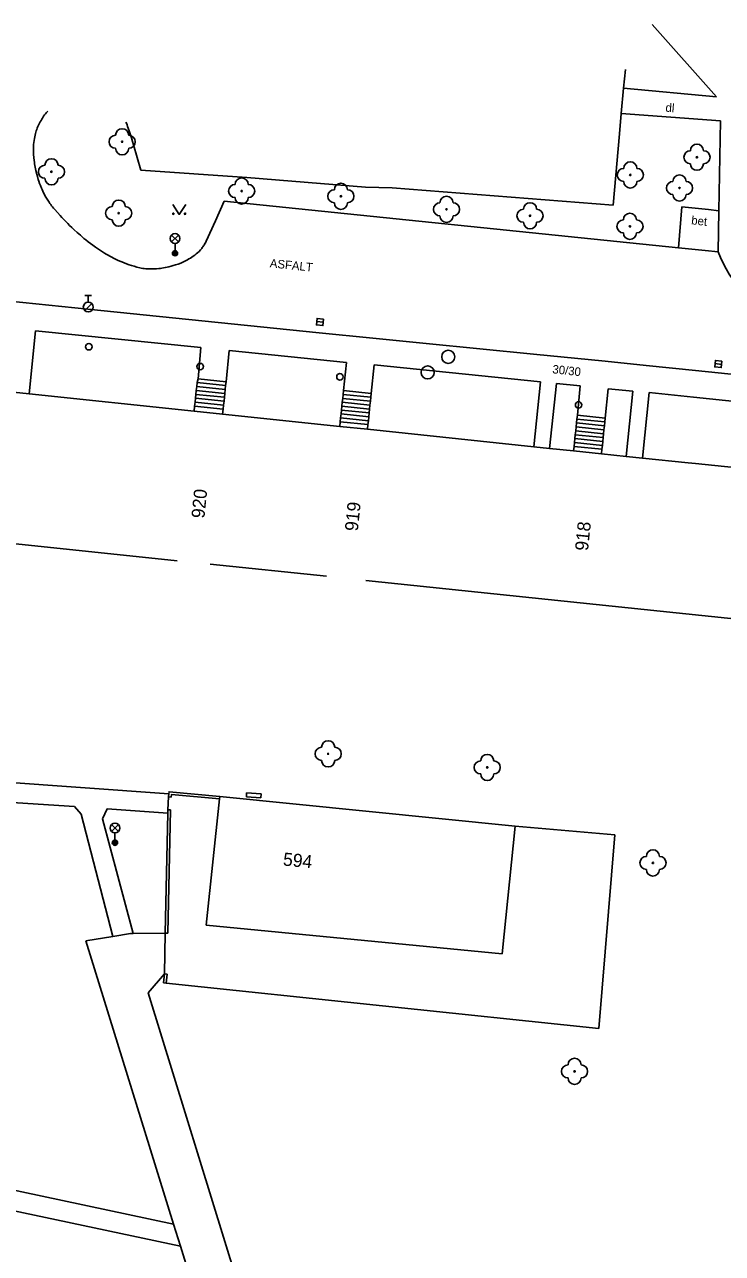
# Model space of a CAD drawing. Extents: x -539244 to -537359, y -1183785 to -1181851.
# Drawn here: x -537529.3 to -537476, y -1181981.5 to -1181887.6 of the extents above; entities that cross this region are included whole.
import ezdxf

# ---------------------------------------------------------------- set-up
doc = ezdxf.new("R2010")
doc.units = 0
for name, color, linetype in [('Vrstva 10', 7, 'Continuous'), ('Vrstva 11', 7, 'Continuous'), ('Vrstva 22', 7, 'Continuous'), ('Vrstva 24', 7, 'Continuous'), ('Vrstva 27', 7, 'Continuous'), ('Vrstva 28', 7, 'Continuous'), ('Vrstva 33', 7, 'Continuous'), ('Vrstva 36', 7, 'Continuous'), ('Vrstva 40', 7, 'Continuous'), ('Vrstva 47', 7, 'Continuous'), ('Vrstva 5', 7, 'Continuous'), ('Vrstva 7', 7, 'Continuous'), ('Vrstva 8', 7, 'Continuous')]:
    doc.layers.add(name, color=color, linetype=linetype)

msp = doc.modelspace()

# ---------------------------------------------------------------- linework, layer by layer
at = {"layer": 'Vrstva 10'}
for p, q in [((-537524.45, -1181909.37), (-537542.12, -1181907.57)), ((-537506.78, -1181911.17), (-537524.45, -1181909.37)), ((-537490.387, -1181912.801), (-537498.584, -1181911.992)), ((-537484.922, -1181913.344), (-537490.387, -1181912.801)), ((-537470.253, -1181914.859), (-537478.01, -1181914.046)), ((-537518.58, -1181960.12), (-537519.84, -1181961.58)), ((-537507.948, -1182000.008), (-537519.84, -1181961.58))]:
    msp.add_line(p, q, dxfattribs=at)
for points in [[(-537528.132, -1181899.754), (-537528.185, -1181899.6), (-537528.227, -1181899.465), (-537528.296, -1181899.228), (-537528.342, -1181899.049), (-537528.405, -1181898.78), (-537528.46, -1181898.51), (-537528.484, -1181898.381), (-537528.505, -1181898.256), (-537528.524, -1181898.133), (-537528.541, -1181898.013), (-537528.567, -1181897.779), (-537528.585, -1181897.558), (-537528.595, -1181897.349), (-537528.597, -1181897.152), (-537528.593, -1181896.966), (-537528.583, -1181896.792), (-537528.568, -1181896.628), (-537528.549, -1181896.475), (-537528.526, -1181896.331), (-537528.5, -1181896.196), (-537528.471, -1181896.069), (-537528.441, -1181895.951), (-537528.41, -1181895.84), (-537528.377, -1181895.737), (-537528.344, -1181895.64), (-537528.31, -1181895.549), (-537528.277, -1181895.464), (-537528.208, -1181895.306), (-537528.141, -1181895.168), (-537528.077, -1181895.048), (-537528.018, -1181894.944), (-537527.963, -1181894.853), (-537527.912, -1181894.774), (-537527.818, -1181894.636), (-537527.742, -1181894.533), (-537527.683, -1181894.457), (-537527.589, -1181894.343), (-537527.49, -1181894.23)], [(-537521.1, -1181906.029), (-537521.293, -1181905.965), (-537521.479, -1181905.898), (-537521.659, -1181905.829), (-537521.833, -1181905.758), (-537522.002, -1181905.686), (-537522.164, -1181905.612), (-537522.321, -1181905.537), (-537522.473, -1181905.462), (-537522.62, -1181905.385), (-537522.762, -1181905.309), (-537522.899, -1181905.233), (-537523.031, -1181905.156), (-537523.159, -1181905.08), (-537523.407, -1181904.927), (-537523.638, -1181904.776), (-537523.853, -1181904.628), (-537524.054, -1181904.484), (-537524.242, -1181904.345), (-537524.418, -1181904.21), (-537524.582, -1181904.08), (-537524.735, -1181903.956), (-537524.879, -1181903.836), (-537525.013, -1181903.722), (-537525.263, -1181903.501), (-537525.48, -1181903.302), (-537525.669, -1181903.123), (-537525.834, -1181902.962), (-537525.978, -1181902.82), (-537526.229, -1181902.563), (-537526.415, -1181902.366), (-537526.555, -1181902.216), (-537526.763, -1181901.985), (-537526.97, -1181901.75), (-537527.054, -1181901.651), (-537527.132, -1181901.555), (-537527.205, -1181901.462), (-537527.274, -1181901.372), (-537527.338, -1181901.285), (-537527.397, -1181901.2), (-537527.507, -1181901.035), (-537527.604, -1181900.88), (-537527.689, -1181900.735), (-537527.763, -1181900.598), (-537527.829, -1181900.47), (-537527.888, -1181900.349), (-537527.94, -1181900.236), (-537527.986, -1181900.13), (-537528.067, -1181899.93), (-537528.132, -1181899.754)], [(-537514.03, -1181901.108), (-537514.7, -1181902.605), (-537515.4, -1181904.17), (-537515.436, -1181904.247), (-537515.475, -1181904.322), (-537515.516, -1181904.394), (-537515.558, -1181904.464), (-537515.602, -1181904.532), (-537515.648, -1181904.597), (-537515.695, -1181904.661), (-537515.743, -1181904.722), (-537515.793, -1181904.781), (-537515.843, -1181904.838), (-537515.948, -1181904.947), (-537516.055, -1181905.049), (-537516.163, -1181905.144), (-537516.274, -1181905.233), (-537516.384, -1181905.315), (-537516.495, -1181905.392), (-537516.606, -1181905.464), (-537516.716, -1181905.53), (-537516.825, -1181905.592), (-537516.933, -1181905.65), (-537517.039, -1181905.703), (-537517.144, -1181905.753), (-537517.246, -1181905.799), (-537517.347, -1181905.842), (-537517.545, -1181905.919), (-537517.734, -1181905.985), (-537517.913, -1181906.041), (-537518.082, -1181906.089), (-537518.241, -1181906.129), (-537518.39, -1181906.163), (-537518.531, -1181906.191), (-537518.662, -1181906.214), (-537518.785, -1181906.233), (-537518.9, -1181906.249), (-537519.007, -1181906.261), (-537519.206, -1181906.279), (-537519.378, -1181906.289), (-537519.526, -1181906.293), (-537519.654, -1181906.293), (-537519.764, -1181906.29), (-537519.859, -1181906.286), (-537520.022, -1181906.273), (-537520.141, -1181906.26), (-537520.229, -1181906.248), (-537520.356, -1181906.226), (-537520.48, -1181906.2), (-537520.694, -1181906.147), (-537520.9, -1181906.09), (-537521.1, -1181906.029)], [(-537514.03, -1181901.108), (-537479.327, -1181904.669), (-537477.276, -1181904.88), (-537476.3, -1181904.98)], [(-537476.3, -1181904.98), (-537476.113, -1181905.419), (-537475.907, -1181905.851), (-537475.682, -1181906.275), (-537475.439, -1181906.689), (-537475.179, -1181907.093), (-537474.901, -1181907.485), (-537474.608, -1181907.865), (-537474.3, -1181908.231), (-537473.977, -1181908.582)], [(-537498.584, -1181911.992), (-537502.682, -1181911.584), (-537506.78, -1181911.17)], [(-537478.01, -1181914.046), (-537481.8, -1181913.658), (-537484.922, -1181913.344)], [(-537524.59, -1181957.61), (-537522.536, -1181957.261), (-537521.18, -1181957.03), (-537520.978, -1181957.029), (-537518.53, -1181957.02)], [(-537511.162, -1182001.003), (-537517.374, -1181980.928), (-537517.896, -1181979.241), (-537524.59, -1181957.61)]]:
    msp.add_lwpolyline(points, dxfattribs=at)
at = {"layer": 'Vrstva 11'}
for p, q in [((-537481.34, -1181887.63), (-537476.42, -1181893.14)), ((-537476.42, -1181893.14), (-537483.512, -1181892.493)), ((-537483.688, -1181894.425), (-537476.11, -1181894.977)), ((-537476.238, -1181901.843), (-537476.11, -1181894.977)), ((-537484.31, -1181901.41), (-537483.83, -1181895.98)), ((-537520.4, -1181898.75), (-537512.3, -1181899.31)), ((-537503.22, -1181900.04), (-537512.3, -1181899.31)), ((-537503.22, -1181900.04), (-537501.18, -1181900.1)), ((-537501.18, -1181900.1), (-537484.31, -1181901.41)), ((-537479.327, -1181904.669), (-537479.07, -1181901.55)), ((-537476.3, -1181904.98), (-537476.238, -1181901.843)), ((-537528.928, -1181915.831), (-537528.43, -1181911.01)), ((-537515.82, -1181912.29), (-537528.43, -1181911.01)), ((-537513.886, -1181914.9), (-537513.64, -1181912.52)), ((-537504.69, -1181913.44), (-537513.64, -1181912.52)), ((-537504.911, -1181915.577), (-537504.69, -1181913.44)), ((-537502.795, -1181915.796), (-537502.57, -1181913.62)), ((-537489.85, -1181914.9), (-537502.57, -1181913.62)), ((-537513.947, -1181915.496), (-537516.127, -1181915.271)), ((-537513.916, -1181915.198), (-537516.096, -1181914.973)), ((-537513.886, -1181914.9), (-537516.02, -1181914.68)), ((-537490.363, -1181919.867), (-537489.85, -1181914.9)), ((-537489.162, -1181919.993), (-537488.65, -1181915.03)), ((-537486.82, -1181915.22), (-537488.65, -1181915.03)), ((-537514.039, -1181916.392), (-537516.219, -1181916.167)), ((-537514.009, -1181916.093), (-537516.189, -1181915.868)), ((-537513.978, -1181915.795), (-537516.158, -1181915.57)), ((-537502.856, -1181916.392), (-537504.972, -1181916.173)), ((-537502.825, -1181916.094), (-537504.941, -1181915.875)), ((-537502.795, -1181915.796), (-537504.911, -1181915.577)), ((-537484.92, -1181917.678), (-537484.69, -1181915.45)), ((-537484.69, -1181915.45), (-537482.8, -1181915.62)), ((-537483.314, -1181920.605), (-537482.8, -1181915.62)), ((-537482.076, -1181920.734), (-537481.56, -1181915.73)), ((-537514.101, -1181916.988), (-537516.281, -1181916.763)), ((-537514.07, -1181916.69), (-537516.25, -1181916.465)), ((-537502.949, -1181917.288), (-537505.065, -1181917.069)), ((-537502.918, -1181916.989), (-537505.034, -1181916.77)), ((-537502.887, -1181916.691), (-537505.003, -1181916.472)), ((-537503.042, -1181918.183), (-537505.158, -1181917.964)), ((-537503.011, -1181917.884), (-537505.127, -1181917.665)), ((-537502.98, -1181917.586), (-537505.096, -1181917.367)), ((-537484.981, -1181918.274), (-537487.112, -1181918.054)), ((-537484.95, -1181917.976), (-537487.082, -1181917.756)), ((-537484.92, -1181917.678), (-537487.03, -1181917.46)), ((-537485.074, -1181919.17), (-537487.205, -1181918.95)), ((-537485.043, -1181918.871), (-537487.174, -1181918.651)), ((-537485.012, -1181918.573), (-537487.143, -1181918.353)), ((-537485.166, -1181920.065), (-537487.297, -1181919.845)), ((-537485.135, -1181919.766), (-537487.267, -1181919.546)), ((-537485.105, -1181919.468), (-537487.236, -1181919.248)), ((-537541.93, -1181944.68), (-537518.255, -1181946.366)), ((-537525.47, -1181947.35), (-537542.09, -1181946.28)), ((-537524.96, -1181947.93), (-537525.47, -1181947.35)), ((-537522.536, -1181957.261), (-537524.96, -1181947.93)), ((-537523.33, -1181948.29), (-537520.978, -1181957.029)), ((-537564.02, -1181969.4), (-537517.896, -1181979.241)), ((-537517.374, -1181980.928), (-537563.82, -1181971.03))]:
    msp.add_line(p, q, dxfattribs=at)
for points in [[(-537483.83, -1181895.98), (-537483.688, -1181894.425), (-537483.512, -1181892.493), (-537483.38, -1181891.05)], [(-537521.528, -1181895.077), (-537521.495, -1181895.157), (-537521.447, -1181895.278), (-537521.404, -1181895.402), (-537521.288, -1181895.756), (-537521.118, -1181896.289), (-537521.037, -1181896.555), (-537520.958, -1181896.823), (-537520.679, -1181897.786), (-537520.4, -1181898.75)], [(-537479.07, -1181901.55), (-537477.026, -1181901.761), (-537476.238, -1181901.843)], [(-537516.02, -1181914.68), (-537515.82, -1181912.29)], [(-537516.321, -1181917.15), (-537516.281, -1181916.763), (-537516.25, -1181916.465), (-537516.219, -1181916.167), (-537516.189, -1181915.868), (-537516.158, -1181915.57), (-537516.127, -1181915.271), (-537516.096, -1181914.973), (-537516.02, -1181914.68)], [(-537514.142, -1181917.378), (-537514.101, -1181916.988), (-537514.07, -1181916.69), (-537514.039, -1181916.392), (-537514.009, -1181916.093), (-537513.978, -1181915.795), (-537513.947, -1181915.496), (-537513.916, -1181915.198), (-537513.886, -1181914.9)], [(-537487.03, -1181917.46), (-537486.82, -1181915.22)], [(-537505.193, -1181918.315), (-537505.158, -1181917.964), (-537505.127, -1181917.665), (-537505.096, -1181917.367), (-537505.065, -1181917.069), (-537505.034, -1181916.77), (-537505.003, -1181916.472), (-537504.972, -1181916.173), (-537504.941, -1181915.875), (-537504.911, -1181915.577)], [(-537503.078, -1181918.536), (-537503.042, -1181918.183), (-537503.011, -1181917.884), (-537502.98, -1181917.586), (-537502.949, -1181917.288), (-537502.918, -1181916.989), (-537502.887, -1181916.691), (-537502.856, -1181916.392), (-537502.825, -1181916.094), (-537502.795, -1181915.796)], [(-537468.89, -1181917.04), (-537478.173, -1181916.08), (-537481.56, -1181915.73)], [(-537487.333, -1181920.184), (-537487.297, -1181919.845), (-537487.267, -1181919.546), (-537487.236, -1181919.248), (-537487.205, -1181918.95), (-537487.174, -1181918.651), (-537487.143, -1181918.353), (-537487.112, -1181918.054), (-537487.082, -1181917.756), (-537487.03, -1181917.46)], [(-537485.202, -1181920.407), (-537485.166, -1181920.065), (-537485.135, -1181919.766), (-537485.105, -1181919.468), (-537485.074, -1181919.17), (-537485.043, -1181918.871), (-537485.012, -1181918.573), (-537484.981, -1181918.274), (-537484.95, -1181917.976), (-537484.92, -1181917.678)], [(-537518.34, -1181947.84), (-537522.96, -1181947.51), (-537523.33, -1181948.29)]]:
    msp.add_lwpolyline(points, dxfattribs=at)
at = {"layer": 'Vrstva 22'}
for centre in [(-537521.82, -1181896.58), (-537477.91, -1181897.76), (-537527.22, -1181898.87), (-537483, -1181899.11), (-537479.24, -1181900.11), (-537512.69, -1181900.34), (-537505.11, -1181900.74), (-537522.08, -1181902.03), (-537497.04, -1181901.74), (-537490.66, -1181902.23), (-537483.03, -1181903.04), (-537506.08, -1181943.32), (-537493.93, -1181944.36), (-537481.27, -1181951.65), (-537487.26, -1181967.57)]:
    msp.add_circle(centre, 0.05, dxfattribs=at)
for centre, start, end in [((-537521.82, -1181896.08), 0, 180), ((-537522.32, -1181896.58), 90, 270), ((-537521.32, -1181896.58), 270, 90), ((-537521.82, -1181897.08), 180, 0), ((-537478.41, -1181897.76), 90, 270), ((-537477.91, -1181897.26), 0, 180), ((-537477.41, -1181897.76), 270, 90), ((-537527.72, -1181898.87), 90, 270), ((-537527.22, -1181898.37), 0, 180), ((-537526.72, -1181898.87), 270, 90), ((-537483, -1181898.61), 0, 180), ((-537477.91, -1181898.26), 180, 0), ((-537512.69, -1181899.84), 0, 180), ((-537483.5, -1181899.11), 90, 270), ((-537482.5, -1181899.11), 270, 90), ((-537479.24, -1181899.61), 0, 180), ((-537527.22, -1181899.37), 180, 0), ((-537513.19, -1181900.34), 90, 270), ((-537512.19, -1181900.34), 270, 90), ((-537505.61, -1181900.74), 90, 270), ((-537505.11, -1181900.24), 0, 180), ((-537504.61, -1181900.74), 270, 90), ((-537483, -1181899.61), 180, 0), ((-537479.74, -1181900.11), 90, 270), ((-537478.74, -1181900.11), 270, 90), ((-537522.08, -1181901.53), 0, 180), ((-537512.69, -1181900.84), 180, 0), ((-537497.04, -1181901.24), 0, 180), ((-537479.24, -1181900.61), 180, 0), ((-537522.58, -1181902.03), 90, 270), ((-537521.58, -1181902.03), 270, 90), ((-537505.11, -1181901.24), 180, 0), ((-537497.54, -1181901.74), 90, 270), ((-537496.54, -1181901.74), 270, 90), ((-537491.16, -1181902.23), 90, 270), ((-537490.66, -1181901.73), 0, 180), ((-537490.16, -1181902.23), 270, 90), ((-537483.03, -1181902.54), 0, 180), ((-537522.08, -1181902.53), 180, 0), ((-537497.04, -1181902.24), 180, 0), ((-537490.66, -1181902.73), 180, 0), ((-537483.53, -1181903.04), 90, 270), ((-537482.53, -1181903.04), 270, 90), ((-537483.03, -1181903.54), 180, 0), ((-537506.08, -1181942.82), 0, 180), ((-537506.58, -1181943.32), 90, 270), ((-537505.58, -1181943.32), 270, 90), ((-537493.93, -1181943.86), 0, 180), ((-537506.08, -1181943.82), 180, 0), ((-537494.43, -1181944.36), 90, 270), ((-537493.43, -1181944.36), 270, 90), ((-537493.93, -1181944.86), 180, 0), ((-537481.27, -1181951.15), 0, 180), ((-537481.77, -1181951.65), 90, 270), ((-537480.77, -1181951.65), 270, 90), ((-537481.27, -1181952.15), 180, 0), ((-537487.26, -1181967.07), 0, 180), ((-537487.76, -1181967.57), 90, 270), ((-537486.76, -1181967.57), 270, 90), ((-537487.26, -1181968.07), 180, 0)]:
    msp.add_arc(centre, 0.5, start, end, dxfattribs=at)
at = {"layer": 'Vrstva 24'}
for p, q in [((-537512.31, -1181946.31), (-537512.326, -1181946.609)), ((-537512.326, -1181946.609), (-537511.226, -1181946.669)), ((-537512.31, -1181946.31), (-537511.21, -1181946.37)), ((-537511.21, -1181946.37), (-537511.226, -1181946.669))]:
    msp.add_line(p, q, dxfattribs=at)
at = {"layer": 'Vrstva 27'}
for p, q in [((-537506.461, -1181910.365), (-537506.959, -1181910.315)), ((-537476.031, -1181913.576), (-537476.529, -1181913.524))]:
    msp.add_line(p, q, dxfattribs=at)
for points in [[(-537506.436, -1181910.116), (-537506.934, -1181910.066), (-537506.984, -1181910.564), (-537506.486, -1181910.614)], [(-537476.005, -1181913.327), (-537476.503, -1181913.275), (-537476.555, -1181913.773), (-537476.057, -1181913.825)]]:
    msp.add_lwpolyline(points, close=True, dxfattribs=at)
for centre in [(-537496.91, -1181913), (-537498.48, -1181914.19)]:
    msp.add_circle(centre, 0.5, dxfattribs=at)
at = {"layer": 'Vrstva 28'}
for p, q in [((-537524.66, -1181908.325), (-537524.16, -1181908.325)), ((-537524.41, -1181908.825), (-537524.41, -1181908.325)), ((-537524.668, -1181909.472), (-537524.138, -1181908.942))]:
    msp.add_line(p, q, dxfattribs=at)
for centre, radius in [((-537524.41, -1181909.2), 0.375), ((-537524.36, -1181912.23), 0.25), ((-537515.86, -1181913.75), 0.25), ((-537505.18, -1181914.53), 0.25), ((-537486.95, -1181916.68), 0.25)]:
    msp.add_circle(centre, radius, dxfattribs=at)
at = {"layer": 'Vrstva 33'}
for p, q in [((-537518.045, -1181904.23), (-537517.515, -1181903.7)), ((-537518.045, -1181903.7), (-537517.515, -1181904.23)), ((-537517.78, -1181904.34), (-537517.78, -1181905.09)), ((-537522.635, -1181949.25), (-537522.105, -1181948.72)), ((-537522.635, -1181948.72), (-537522.105, -1181949.25)), ((-537522.37, -1181949.36), (-537522.37, -1181950.11))]:
    msp.add_line(p, q, dxfattribs=at)
for centre, radius in [((-537517.78, -1181903.965), 0.375), ((-537517.78, -1181905.09), 0.2), ((-537517.78, -1181905.09), 0.145), ((-537517.78, -1181905.09), 0.0876), ((-537522.37, -1181948.985), 0.375), ((-537522.37, -1181950.11), 0.2), ((-537522.37, -1181950.11), 0.145), ((-537522.37, -1181950.11), 0.0876)]:
    msp.add_circle(centre, radius, dxfattribs=at)
at = {"layer": 'Vrstva 36'}
msp.add_lwpolyline([(-537517.959, -1181901.373), (-537517.459, -1181902.123), (-537516.959, -1181901.373)], dxfattribs=at)
for centre in [(-537517.909, -1181902.073), (-537517.01, -1181902.073)]:
    msp.add_circle(centre, 0.05, dxfattribs=at)
at = {"layer": 'Vrstva 5'}
for p, q in [((-537528.928, -1181915.831), (-537530.119, -1181915.706)), ((-537516.321, -1181917.15), (-537528.928, -1181915.831)), ((-537514.142, -1181917.378), (-537516.321, -1181917.15)), ((-537505.193, -1181918.315), (-537514.142, -1181917.378)), ((-537503.078, -1181918.536), (-537505.193, -1181918.315)), ((-537490.363, -1181919.867), (-537503.078, -1181918.536)), ((-537489.162, -1181919.993), (-537490.363, -1181919.867)), ((-537487.333, -1181920.184), (-537489.162, -1181919.993)), ((-537485.202, -1181920.407), (-537487.333, -1181920.184)), ((-537483.314, -1181920.605), (-537485.202, -1181920.407)), ((-537482.076, -1181920.734), (-537483.314, -1181920.605)), ((-537478.575, -1181921.101), (-537482.076, -1181920.734)), ((-537478.01, -1181921.16), (-537478.575, -1181921.101)), ((-537517.623, -1181928.57), (-537541.64, -1181926.063)), ((-537506.209, -1181929.762), (-537515.101, -1181928.834)), ((-537491.8, -1181948.85), (-537514.37, -1181946.57)), ((-537492.79, -1181958.599), (-537491.8, -1181948.85)), ((-537492.79, -1181958.599), (-537515.41, -1181956.4))]:
    msp.add_line(p, q, dxfattribs=at)
for points in [[(-537415.78, -1181927.51), (-537420.372, -1181927.041), (-537422.506, -1181926.824), (-537435.11, -1181925.538), (-537436.32, -1181925.414), (-537438.361, -1181925.206), (-537440.488, -1181924.989), (-537442.323, -1181924.802), (-537443.574, -1181924.674), (-537456.225, -1181923.383), (-537458.336, -1181923.168), (-537467.299, -1181922.253), (-537469.4, -1181922.039), (-537478.01, -1181921.16)], [(-537452.77, -1181935.34), (-537479.492, -1181932.55), (-537503.195, -1181930.076)], [(-537515.41, -1181956.4), (-537514.386, -1181946.757), (-537514.37, -1181946.57)]]:
    msp.add_lwpolyline(points, dxfattribs=at)
at = {"layer": 'Vrstva 7'}
for p, q in [((-537518.081, -1181946.63), (-537518.28, -1181946.61)), ((-537518.33, -1181957.024), (-537518.12, -1181947.594)), ((-537518.32, -1181947.59), (-537518.12, -1181947.594)), ((-537491.8, -1181948.85), (-537484.17, -1181949.5)), ((-537484.17, -1181949.5), (-537485.4, -1181964.3)), ((-537518.53, -1181957.02), (-537518.33, -1181957.024)), ((-537518.58, -1181960.12), (-537518.66, -1181960.8)), ((-537518.58, -1181960.12), (-537518.381, -1181960.143)), ((-537518.381, -1181960.143), (-537518.461, -1181960.823)), ((-537518.66, -1181960.8), (-537518.461, -1181960.823)), ((-537518.461, -1181960.823), (-537485.4, -1181964.3))]:
    msp.add_line(p, q, dxfattribs=at)
for points in [[(-537518.28, -1181946.61), (-537518.255, -1181946.366), (-537518.24, -1181946.22), (-537514.37, -1181946.57)], [(-537514.386, -1181946.757), (-537518.061, -1181946.436), (-537518.081, -1181946.63)], [(-537518.53, -1181957.02), (-537518.34, -1181947.84), (-537518.32, -1181947.59)]]:
    msp.add_lwpolyline(points, dxfattribs=at)
at = {"layer": 'Vrstva 8'}
for p, q in [((-537518.32, -1181947.59), (-537518.28, -1181946.61)), ((-537518.58, -1181960.12), (-537518.53, -1181957.02))]:
    msp.add_line(p, q, dxfattribs=at)

# ---------------------------------------------------------------- texts
at = {"layer": 'Vrstva 40'}
for s, rotation, p in [('dl', 355.45107, (-537480.332, -1181894.277)), ('bet', 354.09317, (-537478.367, -1181902.882)), ('ASFALT', 354.18348, (-537510.56, -1181906.163)), ('30/30', 354.07249, (-537488.975, -1181914.257))]:
    msp.add_text(s, height=0.65, rotation=rotation, dxfattribs=at).set_placement(p)
at = {"layer": 'Vrstva 47'}
for s, rotation, p in [(' 920', 84.1043, (-537515.581, -1181925.739)), (' 919', 84.1043, (-537503.856, -1181926.719)), (' 918', 84.1043, (-537486.274, -1181928.224)), (' 594', 354.20176, (-537509.936, -1181951.806))]:
    msp.add_text(s, height=1, rotation=rotation, dxfattribs=at).set_placement(p)

doc.saveas('drawing.dxf')
